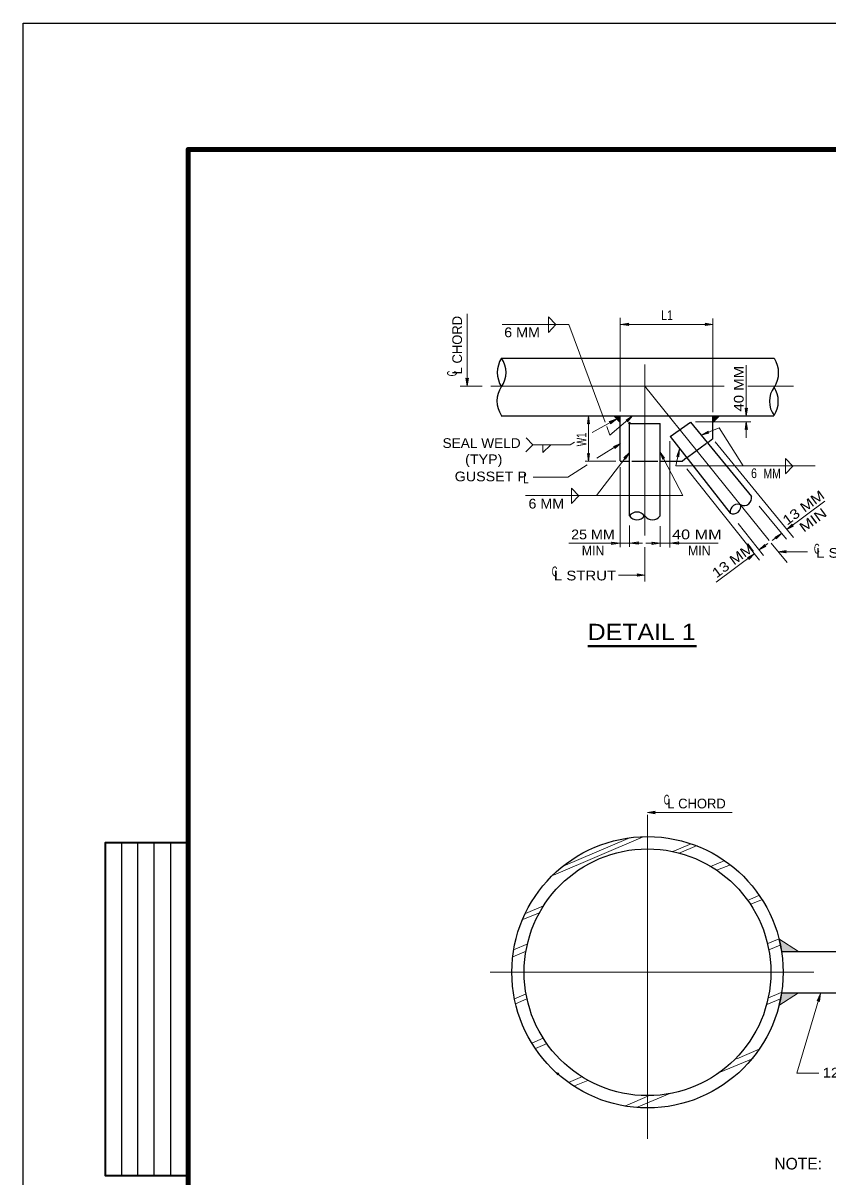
# Model space of a CAD drawing. Extents: x 312601.858 to 312602.699, y 144420.109 to 144420.704.
# Drawn here: x 312601.8578 to 312602.1064, y 144420.3472 to 144420.7035 of the extents above; entities that cross this region are included whole.
import ezdxf
from ezdxf.enums import TextEntityAlignment as Align

# ---------------------------------------------------------------- set-up
doc = ezdxf.new("R2010")
doc.units = 0
doc.header["$LTSCALE"] = 0.0012
doc.header["$PDMODE"] = 32
doc.header["$PDSIZE"] = 0.0006
doc.linetypes.add('DOT_DASHED', pattern=[7.7, 5, -1.2, 0.3, -1.2])
doc.linetypes.add('MEDIUM_DASHED', pattern=[4.5, 3, -1.5])
for name, color, linetype, lineweight in [('1', 7, 'Continuous', 13), ('2', 7, 'Continuous', 13), ('39', 7, 'Continuous', 13), ('60', 7, 'Continuous', 25)]:
    doc.layers.add(name, color=color, linetype=linetype, lineweight=lineweight)

msp = doc.modelspace()

# ---------------------------------------------------------------- hatches: boundary and pattern name
at = {"layer": '2'}
for points in [[(312602.0403, 144420.5822), (312602.0423, 144420.5822), (312602.0423, 144420.5802)], [(312602.0729, 144420.5822), (312602.0709, 144420.5822), (312602.0709, 144420.5802)], [(312602.0921, 144420.4168), (312602.0913, 144420.4207), (312602.0973, 144420.4168)], [(312602.0921, 144420.404), (312602.0913, 144420.4001), (312602.0973, 144420.404)]]:
    msp.add_hatch(color=256, dxfattribs=at).paths.add_polyline_path(points)
at = {"layer": '39'}
for points in [[(312602.0447, 144420.6104), (312602.0449, 144420.6101), (312602.0425, 144420.6104), (312602.0449, 144420.6108)], [(312602.0687, 144420.6104), (312602.0685, 144420.6108), (312602.0709, 144420.6104), (312602.0685, 144420.6101)], [(312601.995, 144420.5936), (312601.9954, 144420.5938), (312601.995, 144420.5914), (312601.9946, 144420.5938)], [(312602.0812, 144420.5844), (312602.0816, 144420.5846), (312602.0812, 144420.5822), (312602.0809, 144420.5846)], [(312602.0325, 144420.58), (312602.0322, 144420.5798), (312602.0325, 144420.5822), (312602.0328, 144420.5798)], [(312602.0393, 144420.5802), (312602.0389, 144420.5805), (312602.0412, 144420.5813), (312602.0393, 144420.5798)], [(312602.0393, 144420.5802), (312602.0389, 144420.5805), (312602.0412, 144420.5813), (312602.0393, 144420.5798)], [(312602.0445, 144420.5808), (312602.0441, 144420.5809), (312602.0461, 144420.5822), (312602.0445, 144420.5804)], [(312602.0812, 144420.5782), (312602.0809, 144420.578), (312602.0812, 144420.5804), (312602.0816, 144420.578)], [(312602.0693, 144420.5771), (312602.0696, 144420.5769), (312602.0673, 144420.5763), (312602.0694, 144420.5775)], [(312602.0693, 144420.5771), (312602.0696, 144420.5769), (312602.0673, 144420.5763), (312602.0694, 144420.5775)], [(312602.0406, 144420.5725), (312602.0402, 144420.5727), (312602.0424, 144420.5737), (312602.0406, 144420.5721)], [(312602.0406, 144420.5725), (312602.0402, 144420.5727), (312602.0424, 144420.5737), (312602.0406, 144420.5721)], [(312602.0602, 144420.5699), (312602.0598, 144420.5697), (312602.0606, 144420.572), (312602.0604, 144420.5696)], [(312602.0602, 144420.5699), (312602.0598, 144420.5697), (312602.0606, 144420.572), (312602.0604, 144420.5696)], [(312602.0325, 144420.5704), (312602.0328, 144420.5706), (312602.0325, 144420.5682), (312602.0322, 144420.5706)], [(312602.0438, 144420.5692), (312602.0434, 144420.5692), (312602.0451, 144420.5709), (312602.0439, 144420.5688)], [(312602.0556, 144420.5691), (312602.0554, 144420.5687), (312602.0546, 144420.571), (312602.056, 144420.5691)], [(312602.0954, 144420.5484), (312602.0958, 144420.5482), (312602.0937, 144420.5471), (312602.0954, 144420.5488)], [(312602.0954, 144420.5484), (312602.0958, 144420.5482), (312602.0937, 144420.5471), (312602.0954, 144420.5488)], [(312602.0904, 144420.5446), (312602.09, 144420.5447), (312602.0921, 144420.5459), (312602.0904, 144420.5442)], [(312602.0869, 144420.5421), (312602.0873, 144420.5419), (312602.0852, 144420.5408), (312602.0869, 144420.5425)], [(312602.0933, 144420.5402), (312602.0935, 144420.5399), (312602.0911, 144420.5402), (312602.0935, 144420.5406)], [(312602.082, 144420.5383), (312602.0816, 144420.5385), (312602.0837, 144420.5396), (312602.082, 144420.5379)], [(312602.0477, 144420.533), (312602.0475, 144420.5334), (312602.0499, 144420.533), (312602.0475, 144420.5327)], [(312602.0529, 144420.4597), (312602.0531, 144420.4593), (312602.0507, 144420.4597), (312602.0531, 144420.4601)], [(312602.0529, 144420.4597), (312602.0531, 144420.4593), (312602.0507, 144420.4597), (312602.0531, 144420.4601)], [(312602.1035, 144420.4017), (312602.1031, 144420.4016), (312602.1041, 144420.4038), (312602.1038, 144420.4014)]]:
    msp.add_hatch(color=256, dxfattribs=at).paths.add_polyline_path(points)

# ---------------------------------------------------------------- linework, layer by layer
at = {"layer": '1'}
for p, q in [((312601.995, 144420.5914), (312601.995, 144420.6137)), ((312602.0201, 144420.6128), (312602.0224, 144420.6104)), ((312602.0201, 144420.6128), (312602.0201, 144420.608)), ((312602.0423, 144420.5836), (312602.0423, 144420.6125)), ((312602.0709, 144420.5834), (312602.0709, 144420.6123)), ((312602.0058, 144420.6104), (312602.0264, 144420.6104)), ((312602.0201, 144420.608), (312602.0224, 144420.6104)), ((312602.0376, 144420.5803), (312602.0264, 144420.6104)), ((312602.0424, 144420.6104), (312602.0709, 144420.6104)), ((312602.0812, 144420.5822), (312602.0812, 144420.5979)), ((312601.9928, 144420.5914), (312601.9996, 144420.5914)), ((312602.0325, 144420.5682), (312602.0325, 144420.5822)), ((312602.0655, 144420.5804), (312602.0826, 144420.5804)), ((312602.0812, 144420.5754), (312602.0812, 144420.5804)), ((312602.0391, 144420.5762), (312602.0381, 144420.5789)), ((312602.0576, 144420.5744), (312602.0576, 144420.5416)), ((312602.0716, 144420.5742), (312602.0958, 144420.5446)), ((312602.0314, 144420.5682), (312602.0409, 144420.5682)), ((312602.0423, 144420.5417), (312602.0423, 144420.5664)), ((312602.0595, 144420.5668), (312602.1025, 144420.5668)), ((312602.0629, 144420.5659), (312602.0853, 144420.5376)), ((312602.0272, 144420.5599), (312602.0295, 144420.5575)), ((312602.0272, 144420.5599), (312602.0272, 144420.5552)), ((312602.013, 144420.5576), (312602.0616, 144420.5576)), ((312602.0272, 144420.5551), (312602.0295, 144420.5575)), ((312602.0852, 144420.5543), (312602.0936, 144420.5441)), ((312602.0451, 144420.5418), (312602.0451, 144420.5484)), ((312602.0546, 144420.5418), (312602.0546, 144420.5482)), ((312602.0787, 144420.549), (312602.0865, 144420.5391)), ((312602.0452, 144420.5429), (312602.0492, 144420.5429)), ((312602.0499, 144420.5311), (312602.0499, 144420.5417)), ((312602.0502, 144420.5429), (312602.0547, 144420.5429)), ((312602.0889, 144420.5429), (312602.0938, 144420.5369)), ((312602.0911, 144420.5402), (312602.1001, 144420.5402)), ((312602.0417, 144420.533), (312602.0499, 144420.533)), ((312602.0769, 144420.4597), (312602.0507, 144420.4597))]:
    msp.add_line(p, q, dxfattribs=at)
at = {"layer": '1', "lineweight": 25}
for p, q in [((312602.0056, 144420.6), (312602.0898, 144420.6)), ((312602.0055, 144420.5822), (312602.0897, 144420.5822)), ((312602.0423, 144420.5683), (312602.0423, 144420.5822)), ((312602.0451, 144420.5799), (312602.0546, 144420.5799)), ((312602.0451, 144420.5513), (312602.0451, 144420.5799)), ((312602.0546, 144420.5513), (312602.0546, 144420.5799)), ((312602.0577, 144420.5758), (312602.064, 144420.5803)), ((312602.064, 144420.5803), (312602.0828, 144420.5573)), ((312602.0709, 144420.5751), (312602.0709, 144420.5822)), ((312602.0577, 144420.5758), (312602.0762, 144420.5522)), ((312602.0709, 144420.5751), (312602.0693, 144420.5739)), ((312602.0628, 144420.5692), (312602.0615, 144420.5682)), ((312602.0423, 144420.5682), (312602.0452, 144420.5682)), ((312602.0547, 144420.5682), (312602.0615, 144420.5682)), ((312602.0921, 144420.4168), (312602.1881, 144420.4168)), ((312602.0921, 144420.404), (312602.1881, 144420.404))]:
    msp.add_line(p, q, dxfattribs=at)
at = {"layer": '1', "linetype": 'DOT_DASHED'}
for p, q in [((312602.0499, 144420.5453), (312602.0499, 144420.5981)), ((312602.0023, 144420.5914), (312602.0744, 144420.5914)), ((312602.0498, 144420.5915), (312602.0883, 144420.5437)), ((312602.0817, 144420.5914), (312602.0958, 144420.5914))]:
    msp.add_line(p, q, dxfattribs=at)
at = {"layer": '1', "linetype": 'MEDIUM_DASHED', "lineweight": 25}
for p, q in [((312602.0689, 144420.5737), (312602.0631, 144420.5694)), ((312602.0459, 144420.5682), (312602.0539, 144420.5682))]:
    msp.add_line(p, q, dxfattribs=at)
at = {"layer": '1', "lineweight": 40}
msp.add_line((312602.0323, 144420.5111), (312602.0658, 144420.5111), dxfattribs=at)
at = {"layer": '1'}
for points in [[(312602.0673, 144420.5763), (312602.0728, 144420.5785), (312602.0803, 144420.5668)], [(312602.0264, 144420.5429), (312602.0423, 144420.5429), (312602.0452, 144420.5429)], [(312602.0547, 144420.5429), (312602.0577, 144420.5429), (312602.0725, 144420.5429)]]:
    msp.add_lwpolyline(points, dxfattribs=at)
for points in [[(312602.0396, 144420.5432), (312602.0423, 144420.5429), (312602.0396, 144420.5425), (312602.0399, 144420.5429)], [(312602.0479, 144420.5426), (312602.0452, 144420.5429), (312602.0479, 144420.5433), (312602.0476, 144420.5429)], [(312602.052, 144420.5432), (312602.0547, 144420.5429), (312602.052, 144420.5425), (312602.0523, 144420.5429)], [(312602.0604, 144420.5426), (312602.0577, 144420.5429), (312602.0604, 144420.5433), (312602.0601, 144420.5429)]]:
    msp.add_lwpolyline(points, close=True, dxfattribs=at)
at = {"layer": '1', "lineweight": 25}
for radius in [0.0418919, 0.0381]:
    msp.add_circle((312602.0507, 144420.4104), radius, dxfattribs=at)
at = {"layer": '1'}
msp.add_point((312602.0451, 144420.58), dxfattribs=at)
at = {"layer": '2'}
for p, q in [((312602.0336, 144420.5771), (312602.0412, 144420.5813)), ((312602.0461, 144420.5822), (312602.0391, 144420.5762)), ((312602.0131, 144420.5711), (312602.0153, 144420.5733)), ((312602.0132, 144420.5754), (312602.0153, 144420.5733)), ((312602.0268, 144420.5733), (312602.0153, 144420.5733)), ((312602.0184, 144420.5709), (312602.0184, 144420.5733)), ((312602.0207, 144420.5732), (312602.0184, 144420.5709)), ((312602.0268, 144420.5733), (312602.0282, 144420.5741)), ((312602.0424, 144420.5737), (312602.0351, 144420.5691)), ((312602.0595, 144420.5668), (312602.0606, 144420.572)), ((312602.0451, 144420.5709), (312602.0349, 144420.5576)), ((312602.0546, 144420.571), (312602.0616, 144420.5576)), ((312602.0321, 144420.5671), (312602.0261, 144420.5633)), ((312602.0261, 144420.5633), (312602.0154, 144420.5633)), ((312602.1055, 144420.5559), (312602.0937, 144420.5471)), ((312602.0921, 144420.5459), (312602.0892, 144420.5437)), ((312602.0879, 144420.5428), (312602.0852, 144420.5408)), ((312602.0837, 144420.5396), (312602.0719, 144420.5309)), ((312602.0217, 144420.4404), (312602.0494, 144420.4522)), ((312602.0246, 144420.4432), (312602.0447, 144420.4517)), ((312602.0585, 144420.4477), (312602.0642, 144420.4501)), ((312602.0605, 144420.4472), (312602.066, 144420.4495)), ((312602.07, 144420.443), (312602.0746, 144420.4449)), ((312602.0723, 144420.442), (312602.0763, 144420.4436)), ((312602.0816, 144420.4326), (312602.0851, 144420.4341)), ((312602.013, 144420.4285), (312602.0186, 144420.4309)), ((312602.0826, 144420.4314), (312602.0859, 144420.4328)), ((312602.0122, 144420.4267), (312602.0175, 144420.4289)), ((312602.0093, 144420.4173), (312602.0137, 144420.4192)), ((312602.0879, 144420.4193), (312602.0914, 144420.4207)), ((312602.0882, 144420.4173), (312602.0917, 144420.4188)), ((312602.0091, 144420.4152), (312602.0132, 144420.4169)), ((312602.0096, 144420.4022), (312602.0132, 144420.4037)), ((312602.0099, 144420.4007), (312602.0134, 144420.4022)), ((312602.0876, 144420.4004), (312602.0918, 144420.4022)), ((312602.0879, 144420.4024), (312602.092, 144420.4041)), ((312602.015, 144420.3885), (312602.0185, 144420.39)), ((312602.0161, 144420.3869), (312602.0197, 144420.3884)), ((312602.0731, 144420.3795), (312602.0833, 144420.3838)), ((312602.0783, 144420.3837), (312602.0852, 144420.3866)), ((312602.0263, 144420.3764), (312602.0306, 144420.3782)), ((312602.0282, 144420.3753), (312602.0323, 144420.377)), ((312602.0437, 144420.3691), (312602.0515, 144420.3724)), ((312602.0473, 144420.3686), (312602.0576, 144420.373))]:
    msp.add_line(p, q, dxfattribs=at)
at = {"layer": '2', "linetype": 'DOT_DASHED'}
for p, q in [((312602.0507, 144420.359), (312602.0507, 144420.4624)), ((312602.0021, 144420.4104), (312602.2652, 144420.4104))]:
    msp.add_line(p, q, dxfattribs=at)
at = {"layer": '2'}
for points in [[(312602.0403, 144420.5822), (312602.0423, 144420.5822), (312602.0423, 144420.5802)], [(312602.0729, 144420.5822), (312602.0709, 144420.5822), (312602.0709, 144420.5802)], [(312602.0921, 144420.4168), (312602.0913, 144420.4207), (312602.0973, 144420.4168)], [(312602.0921, 144420.404), (312602.0913, 144420.4001), (312602.0973, 144420.404)]]:
    msp.add_lwpolyline(points, close=True, dxfattribs=at)
for points in [[(312602.0933, 144420.5644), (312602.0933, 144420.569), (312602.0956, 144420.5667), (312602.0933, 144420.5643)], [(312602.1036, 144420.3792), (312602.0968, 144420.3792), (312602.1041, 144420.4038)]]:
    msp.add_lwpolyline(points, dxfattribs=at)
at = {"layer": '2', "lineweight": 25}
for centre, radius, start, end in [((312602.012392, 144420.5956), 0.0080929, 147.06517, 212.93482), ((312601.999386, 144420.5956), 0.0076143, 324.69975, 35.30025), ((312602.083108, 144420.5955), 0.0080929, 327.06517, 32.93482), ((312602.012292, 144420.5868), 0.0080929, 147.06517, 212.93482), ((312602.096014, 144420.5867), 0.0076143, 144.69975, 215.30025), ((312602.083008, 144420.5867), 0.0080929, 327.06517, 32.93482), ((312602.078557, 144420.552542), 0.0023616, 59.08787, 188.12786), ((312602.077212, 144420.554329), 0.0023576, 244.56713, 14.01168), ((312602.080487, 144420.556861), 0.0023752, 245.45097, 13.12784), ((312602.04745, 144420.549625), 0.0028858, 34.91183, 144.52002), ((312602.04745, 144420.552975), 0.0028858, 215.47998, 324.52002), ((312602.05225, 144420.552975), 0.0028858, 215.47998, 324.52002)]:
    msp.add_arc(centre, radius, start, end, dxfattribs=at)
at = {"layer": '2'}
msp.add_point((312602.023, 144420.379), dxfattribs=at)
at = {"layer": '39', "lineweight": 25}
for p, q in [((312601.8578, 144420.7035), (312602.6988, 144420.7035)), ((312601.8578, 144420.1095), (312601.8578, 144420.7035))]:
    msp.add_line(p, q, dxfattribs=at)
at = {"layer": '39', "lineweight": 158}
msp.add_lwpolyline([(312601.9088, 144420.1247), (312601.9088, 144420.6645), (312602.6838, 144420.6645)], dxfattribs=at)
at = {"layer": '39'}
for points in [[(312602.0447, 144420.6104), (312602.0449, 144420.6101), (312602.0425, 144420.6104), (312602.0449, 144420.6108)], [(312602.0687, 144420.6104), (312602.0685, 144420.6108), (312602.0709, 144420.6104), (312602.0685, 144420.6101)], [(312601.995, 144420.5936), (312601.9954, 144420.5938), (312601.995, 144420.5914), (312601.9946, 144420.5938)], [(312602.0812, 144420.5844), (312602.0816, 144420.5846), (312602.0812, 144420.5822), (312602.0809, 144420.5846)], [(312602.0325, 144420.58), (312602.0322, 144420.5798), (312602.0325, 144420.5822), (312602.0328, 144420.5798)], [(312602.0393, 144420.5802), (312602.0389, 144420.5805), (312602.0412, 144420.5813), (312602.0393, 144420.5798)], [(312602.0393, 144420.5802), (312602.0389, 144420.5805), (312602.0412, 144420.5813), (312602.0393, 144420.5798)], [(312602.0445, 144420.5808), (312602.0441, 144420.5809), (312602.0461, 144420.5822), (312602.0445, 144420.5804)], [(312602.0812, 144420.5782), (312602.0809, 144420.578), (312602.0812, 144420.5804), (312602.0816, 144420.578)], [(312602.0693, 144420.5771), (312602.0696, 144420.5769), (312602.0673, 144420.5763), (312602.0694, 144420.5775)], [(312602.0693, 144420.5771), (312602.0696, 144420.5769), (312602.0673, 144420.5763), (312602.0694, 144420.5775)], [(312602.0406, 144420.5725), (312602.0402, 144420.5727), (312602.0424, 144420.5737), (312602.0406, 144420.5721)], [(312602.0406, 144420.5725), (312602.0402, 144420.5727), (312602.0424, 144420.5737), (312602.0406, 144420.5721)], [(312602.0602, 144420.5699), (312602.0598, 144420.5697), (312602.0606, 144420.572), (312602.0604, 144420.5696)], [(312602.0602, 144420.5699), (312602.0598, 144420.5697), (312602.0606, 144420.572), (312602.0604, 144420.5696)], [(312602.0325, 144420.5704), (312602.0328, 144420.5706), (312602.0325, 144420.5682), (312602.0322, 144420.5706)], [(312602.0438, 144420.5692), (312602.0434, 144420.5692), (312602.0451, 144420.5709), (312602.0439, 144420.5688)], [(312602.0556, 144420.5691), (312602.0554, 144420.5687), (312602.0546, 144420.571), (312602.056, 144420.5691)], [(312602.0954, 144420.5484), (312602.0958, 144420.5482), (312602.0937, 144420.5471), (312602.0954, 144420.5488)], [(312602.0954, 144420.5484), (312602.0958, 144420.5482), (312602.0937, 144420.5471), (312602.0954, 144420.5488)], [(312602.0904, 144420.5446), (312602.09, 144420.5447), (312602.0921, 144420.5459), (312602.0904, 144420.5442)], [(312602.0869, 144420.5421), (312602.0873, 144420.5419), (312602.0852, 144420.5408), (312602.0869, 144420.5425)], [(312602.0933, 144420.5402), (312602.0935, 144420.5399), (312602.0911, 144420.5402), (312602.0935, 144420.5406)], [(312602.082, 144420.5383), (312602.0816, 144420.5385), (312602.0837, 144420.5396), (312602.082, 144420.5379)], [(312602.0477, 144420.533), (312602.0475, 144420.5334), (312602.0499, 144420.533), (312602.0475, 144420.5327)], [(312602.0529, 144420.4597), (312602.0531, 144420.4593), (312602.0507, 144420.4597), (312602.0531, 144420.4601)], [(312602.0529, 144420.4597), (312602.0531, 144420.4593), (312602.0507, 144420.4597), (312602.0531, 144420.4601)], [(312602.1035, 144420.4017), (312602.1031, 144420.4016), (312602.1041, 144420.4038), (312602.1038, 144420.4014)]]:
    msp.add_lwpolyline(points, close=True, dxfattribs=at)
at = {"layer": '60'}
for p, q in [((312601.8883, 144420.3475), (312601.8883, 144420.4505)), ((312601.8933, 144420.3475), (312601.8933, 144420.4505)), ((312601.8983, 144420.3475), (312601.8983, 144420.4505)), ((312601.9034, 144420.3475), (312601.9034, 144420.4505))]:
    msp.add_line(p, q, dxfattribs=at)
at = {"layer": '60', "lineweight": 35}
msp.add_lwpolyline([(312601.9084, 144420.3475), (312601.8833, 144420.3475), (312601.8833, 144420.4505), (312601.9084, 144420.4505)], dxfattribs=at)

# ---------------------------------------------------------------- texts
at = {"layer": '2'}
for s, height, width, p in [('L1', 0.003, 0.8, (312602.05675, 144420.6118)), ('6 MM', 0.003, 1.1, (312602.01195, 144420.6065)), ('SEAL WELD', 0.003, 1.05, (312601.99945, 144420.5723)), (' (TYP)', 0.003, 1.1, (312601.9995, 144420.5673)), ('GUSSET P', 0.003, 1.1, (312602.0023, 144420.562)), ('6', 0.003, 0.8, (312602.0836, 144420.563)), ('MM', 0.003, 0.8, (312602.0892, 144420.5629)), ('L', 0.003, 0.75, (312602.01315, 144420.5614)), ('6 MM', 0.003, 1.1, (312602.01945, 144420.5536)), ('25 MM', 0.003, 1.1, (312602.03385, 144420.5441)), ('40 MM ', 0.003, 1.25, (312602.06665, 144420.5441)), ('MIN', 0.003, 0.95, (312602.0339, 144420.5391)), ('MIN', 0.003, 0.95, (312602.0667, 144420.5391)), ('C', 0.003, 0.6, (312602.103, 144420.5397)), ('L STRUT', 0.003, 1.15, (312602.1124, 144420.5384)), ('C', 0.003, 0.6, (312602.022, 144420.5327)), ('L STRUT', 0.003, 1.15, (312602.0314, 144420.5314)), ('DETAIL 1', 0.005, 1.15, (312602.0489, 144420.513)), ('C', 0.003, 0.6, (312602.0566, 144420.4622)), ('12 MM GUSSET PLATE', 0.003, 1.15, (312602.12995, 144420.3779))]:
    msp.add_text(s, height=height, dxfattribs=dict(at, width=width)).set_placement(p, align=Align.CENTER)
msp.add_text('L CHORD', height=0.003, rotation=90, dxfattribs=at).set_placement((312601.9934, 144420.60405), align=Align.CENTER)
for s, height, rotation, width, p in [('40 MM', 0.003, 90, 1.15, (312602.0804, 144420.5906)), ('C', 0.003, 90, 0.6, (312601.9918, 144420.5953)), ('W1', 0.002999, 90, 0.7, (312602.0318, 144420.5749)), ('13 MM', 0.003, 36.375, 1.2, (312602.09976, 144420.552664)), ('MIN', 0.003, 36.375, 1.25, (312602.10271, 144420.548833)), ('13 MM', 0.003, 36.375, 1.2, (312602.07796, 144420.536364))]:
    msp.add_text(s, height=height, rotation=rotation, dxfattribs=dict(at, width=width)).set_placement(p, align=Align.CENTER)
msp.add_text('L CHORD', height=0.003, dxfattribs=at).set_placement((312602.06585, 144420.461), align=Align.CENTER)
msp.add_text('NOTE:', height=0.0036, dxfattribs=at).set_placement((312602.0899, 144420.3495))

doc.saveas('drawing.dxf')
